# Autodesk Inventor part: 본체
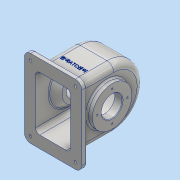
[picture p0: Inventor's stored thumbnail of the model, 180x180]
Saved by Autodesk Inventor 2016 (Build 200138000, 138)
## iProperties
Created: 2018-11
Part Number: 본체
Material: 알루미늄 6061
Document SubType Name: Modeling
Designer: 공506_41
Density: 2.7 g/cm^3
Appearance: 알루미늄 - 평지
Mass: 1091.96 g
Surface Area: 1182.19 cm^2
Volume: 404.431 cm^3
Author: 공506_41
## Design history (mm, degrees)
sketch "스케치1"
  geometry: L1 (-55, 75)-(55, 75); L2 (55, 75)-(55, -75); L3 (55, -75)-(-55, -75); L4 (-55, -75)-(-55, 75); L5 (-55, 75)-(55, -75); L6 (55, 75)-(-55, -75); 1 further point
  constraints: 12 end point, 2 midpoint, 2 parallel, 1 horizontal, 1 perpendicular
  dimensions: "d0" = 110 distance of L2.end L3.end; "d1" = 150 distance of L1.end L2.end
extrude "돌출1" new body sketch "스케치1" distance "d2" = 10; taper "d3" = 0 deg
sketch "스케치5"
  geometry: L1 (-38.5, -58)-(38.5, -58); L2 (38.5, -58)-(38.5, 58); L3 (38.5, 58)-(-38.5, 58); L4 (-38.5, 58)-(-38.5, -58); L5 (-38.5, -58)-(38.5, 58); L6 (38.5, -58)-(-38.5, 58); 1 further point
  constraints: 12 end point, 2 midpoint, 2 parallel, 1 horizontal, 1 perpendicular
  dimensions: "d6" = 77 distance of L3.end L2.end; "d7" = 116 distance of L2.end L1.end
extrude "돌출2" join sketch "스케치5" distance "d8" = 126; taper "d9" = 0 deg
sketch "스케치7"
  geometry: L1 (133, -10)-(-17, -10) reference; C1 r 38 at (58, 55); 2 further points
  constraints: 1 centre point, 1 midpoint, 1 vertical alignment
  dimensions: "d10" = 76 diameter of C1; "d11" = 65 distance from line of C1.centre L1
extrude "돌출3" join sketch "스케치7" distance "d12" = 5; taper "d13" = 0 deg
sketch "스케치8"
  geometry: C1 r 20 at (0, 0); 1 further point
  constraints: 1 centre point
  dimensions: "d14" = 40 diameter of C1
extrude "돌출4" cut sketch "스케치8" distance "d15" = 24; taper "d16" = 0 deg
sketch "스케치9"
  geometry: L1 (133, -10)-(-17, -10) reference; C1 r 38 at (58, 55); 2 further points
  constraints: 1 centre point, 1 midpoint, 1 vertical alignment
  dimensions: "d17" = 76 diameter of C1; "d18" = 65 distance from line of L1 C1.centre
extrude "돌출5" join sketch "스케치9" distance "d19" = 10; taper "d20" = 0 deg
sketch "스케치10"
  geometry: C1 r 20 at (0, 0); C2 r 38 at (0, 0) reference; 1 further point
  constraints: 1 centre point, 1 concentric
  dimensions: "d21" = 40 diameter of C1
extrude "돌출6" cut sketch "스케치10" distance "d22" = 100; taper "d23" = 0 deg
fillet "모깎기1" dims "d24" = 58
sketch "스케치11" dims "d88" = 13
  geometry: L1 (10, 58)-(78, 58) reference; L2 (10, -58)-(78, -58) reference; L3 (0, 52)-(78, 52); L4 (78, -52)-(0, -52); L5 (0, 75)-(0, -75) reference; L6 (0, 52)-(0, -52); A1 r 58 centre (78, 0) between (78, -58) and (78, 58) reference; A2 r 52 centre (78, 0) between (78, -52) and (78, 52); 1 further point
  constraints: 6 end point, 2 horizontal, 2 point on circle, 2 point on line, 2 tangent, 1 centre point, 1 vertical
  dimensions: "d25" = 6 radial gap between concentric circles of A1 A2
extrude "돌출7" cut sketch "스케치11" stored distance "d26" = 67; taper "d27" = 0 deg
sketch "스케치12"
  geometry: C1 r 38 at (0, 0) reference; 2 further points
  constraints: 1 vertical alignment
  dimensions: "d29" = 29 distance of C1.centre point (0, 29)
hole "구멍1" sketch "스케치12" at (0, 29) diameter "d30" = 3.242; stored, may be unused: countersink angle "d34" = 90 deg, drill point angle "d36" = 118 deg; dims "d31" = 8, "d32" = 4, "d33" = 2, "d35" = 10
sketch "스케치13"
  geometry: C1 r 1.621 at (0, 29) reference; C2 r 38 at (0, 0) reference; 2 further points
  constraints: 1 coincident
  dimensions: "d40" = 29 distance of C2.centre point (0, 29) (derived)
hole "구멍2" sketch "스케치13" at (0, 29) diameter "d41" = 3.242; stored, may be unused: countersink angle "d45" = 90 deg, drill point angle "d47" = 118 deg; dims "d42" = 8, "d43" = 4, "d44" = 2, "d46" = 10
node "작업 평면1"
sketch "스케치14"
  geometry: C1 r 28 at (0, 0); C2 r 20 at (0, 0) reference; 1 further point
  constraints: 1 centre point, 1 concentric
  dimensions: "d52" = 56 diameter of C1
extrude "돌출8" join sketch "스케치14" distance "d53" = 14; taper "d54" = 40 deg
sketch "스케치15"
  geometry: C1 r 20 at (0, 0) reference; 1 further point
extrude "돌출9" cut sketch "스케치15" stored distance "d55" = 14; taper "d56" = 0 deg
sketch "스케치16"
  geometry: L1 (-55, 75)-(-55, -75) reference; L2 (-55, -75)-(55, -75) reference; C1 r 6 at (-43, -63); 1 further point
  constraints: 1 centre point
  dimensions: "d57" = 12 diameter of C1; "d58" = 12 distance from line of C1.centre L1; "d59" = 12 distance from line of C1.centre L2
extrude "돌출10" cut sketch "스케치16" distance "d60" = 4; taper "d61" = 0 deg
sketch "스케치17"
  geometry: C1 r 6 at (0, 0) reference; C2 r 2.5 at (0, 0); 1 further point
  constraints: 1 centre point, 1 coincident
  dimensions: "d62" = 5 diameter of C2
extrude "돌출11" cut sketch "스케치17" stored distance "d63" = 4; taper "d64" = 0 deg
node "작업 평면2"
sketch "스케치18"
  geometry: C1 r 6 at (0, 0); 1 further point
  constraints: 1 centre point, 1 coincident
  dimensions: "d72" = 12 diameter of C1
extrude "돌출12" join sketch "스케치18" stored distance "d73" = 4; taper "d74" = 5 deg
sketch "스케치19"
  geometry: 2 further points
  constraints: 1 coincident
hole "구멍3" sketch "스케치19" at (0, 0) diameter "d75" = 4.459; stored, may be unused: countersink angle "d79" = 90 deg, drill point angle "d81" = 118 deg; dims "d76" = 20, "d77" = 4, "d78" = 2, "d80" = 20
sketch "스케치20"
  geometry: L1 (93.5, -10)-(-16.5, -10) reference; L2 (0, 0)-(0, 68) reference; 2 further points
  constraints: 1 other
  dimensions: "d82" = 40 distance from line of L1 point (38.5, 30); "d83" = 38.5 distance from line of point (38.5, 30) L2
feature "엠보싱1" sketch "스케치20" dims "d84" = 0.5, "d85" = 0
fillet "모깎기2" dims "d86" = 12
fillet "모깎기3" dims "d87" = 3
fillet "모깎기4" dims "d88" = 13
fillet "모깎기5" dims "d89" = 3
fillet "모깎기6" dims "d90" = 3
fillet "모깎기7" dims "d91" = 3
fillet "모깎기8" dims "d92" = 3
chamfer "모따기1" distance "d93" = 1; stored, may be unused: second distance "d94" = 2, angle "d95" = 45 deg
chamfer "모따기2" distance "d96" = 1; stored, may be unused: second distance "d97" = 2, angle "d98" = 45 deg
fillet "모깎기9" dims "d99" = 8
fillet "모깎기10" dims "d100" = 3
node "솔리드1"
pattern_circular "원형 패턴1" dims angle "d38" = 360 deg
pattern_circular "원형 패턴2" dims angle "d49" = 360 deg
pattern_linear "직사각형 패턴1" dims "d67" = 126, "d70" = 86
other parameters: "d51" = -24, "d71" = 142
